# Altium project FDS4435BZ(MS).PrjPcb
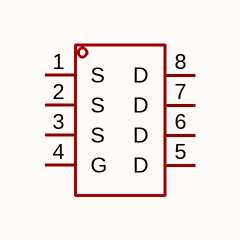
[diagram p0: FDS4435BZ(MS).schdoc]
1 sheet, 1 parts. Net scope: global (net labels, ports and power ports of the same name join across sheets).

## Sheet FDS4435BZ(MS).schdoc
size 127 x 101 mm

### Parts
Q?  fds4435bz(ms)  [SOIC-8_L4.9-W3.9-P1.27-LS6.0-BL]  (value not drawn)

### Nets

Not connected (* = marked no-connect by the designer): Q? 1(S) 2(S) 3(S) 4(G) 5(D) 6(D) 7(D) 8(D)

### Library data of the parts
Q? = fds4435bz(ms): 数量:1个P沟道;漏源电压(Vdss):30V;连续漏极电流(Id):9A;导通电阻(RDS(on)):22mΩ@10V;耗散功率(Pd):2.1W;阈值电压(Vgs(th)):2.5V;; Manufacturer: MSKSEMI(美森科); AddInBom: yes; ModelId: e81d2f7d937b4a6ab1dca543ff5d56a4; ModelName: SOIC-8_L4.9-W3.9-H1.7-LS6.0-P1.27; ModelTransform: 192.913,236.22,0,0,0,0,0,0,0; Number: 1个P沟道; Drain to Source Voltage: 30V; Current - Continuous Drain(Id): 9A; Pd - Power Dissipation: 2.1W; Gate Threshold Voltage (Vgs(th)): 2.5V; Gate Charge(Qg): 11nC@4.5V; Input Capacitance(Ciss): 1.25nF; Reverse Transfer Capacitance (Crss@Vds): 90pF; Output Capacitance(Coss): 160pF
